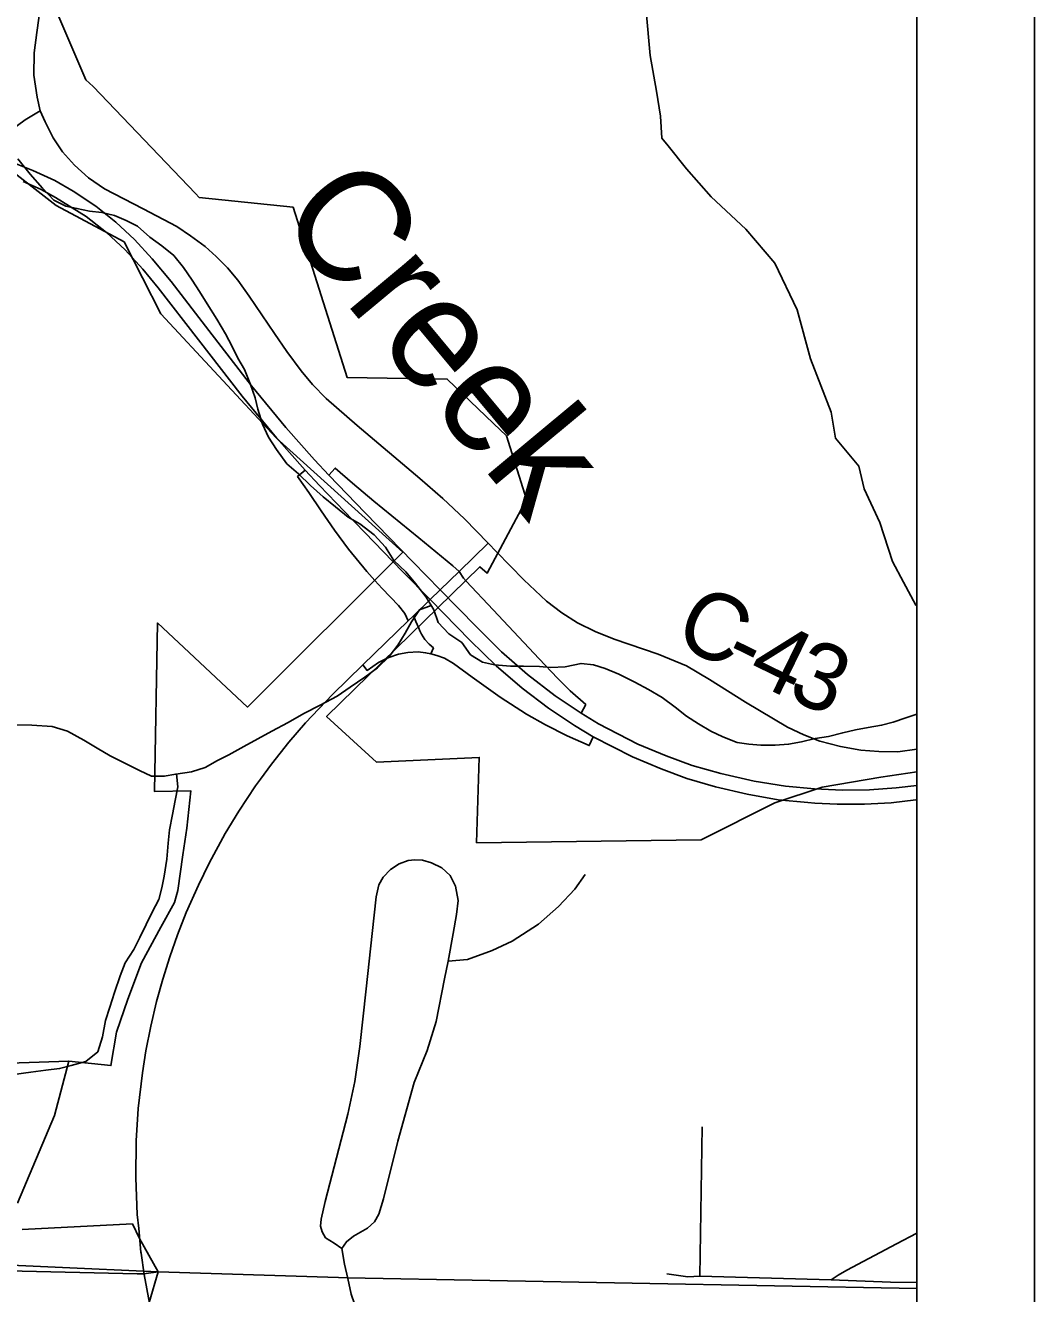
# Model space of a CAD drawing. Extents: x 0 to 34, y 0 to 22.
# Drawn here: x 8.143 to 9, y 15.691 to 16.768 of the extents above; entities that cross this region are included whole.
import ezdxf

# ---------------------------------------------------------------- set-up
doc = ezdxf.new("R2010")
doc.units = 0
for name, color, linetype in [('GM_X_City_Street', 7, 'Continuous'), ('GM_X_Corporation', 7, 'Continuous'), ('GM_X_County_Road', 7, 'Continuous'), ('GM_X_County_Road_Text', 7, 'Continuous'), ('GM_X_Interchange_Ramps', 7, 'Continuous'), ('GM_X_Minor_River', 7, 'Continuous'), ('GM_X_Minor_River_Text', 7, 'Continuous'), ('GM_X_Township_Road', 7, 'Continuous'), ('GM_X_US_Route', 7, 'Continuous'), ('SH_Data', 7, 'Continuous')]:
    doc.layers.add(name, color=color, linetype=linetype)

msp = doc.modelspace()

# ---------------------------------------------------------------- linework, layer by layer
at = {"layer": 'GM_X_City_Street'}
msp.add_line((8.7156, 15.7058), (8.7176, 15.8327), dxfattribs=at)
for points in [[(8.4116, 15.7295), (8.4052, 15.734), (8.3978, 15.7385), (8.3949, 15.7435), (8.3935, 15.7485), (8.394, 15.7542), (8.3975, 15.7693), (8.4166, 15.8435), (8.4228, 15.8711), (8.4269, 15.9008), (8.4323, 15.95), (8.4374, 15.997), (8.4408, 16.028), (8.443, 16.0382), (8.4468, 16.0448), (8.4531, 16.0513), (8.4603, 16.056), (8.4681, 16.059), (8.4737, 16.0596), (8.4801, 16.0593), (8.4879, 16.0569), (8.4967, 16.0527), (8.5037, 16.0461), (8.5083, 16.037), (8.5103, 16.025), (8.5091, 16.0131), (8.5063, 15.997), (8.5019, 15.9735)], [(8.4116, 15.7295), (8.4156, 15.7351), (8.4215, 15.74), (8.4334, 15.7467), (8.4393, 15.7521), (8.4431, 15.7586), (8.4471, 15.7716), (8.4592, 15.8206), (8.473, 15.8705), (8.4842, 15.8975), (8.4918, 15.9222), (8.4987, 15.9583), (8.5019, 15.9735), (8.5184, 15.9748), (8.5392, 15.9826), (8.5563, 15.9905), (8.5787, 16.0048), (8.5957, 16.0199), (8.6095, 16.0345), (8.6183, 16.0469)], [(8.8272, 15.7027), (8.8332, 15.7068), (8.8405, 15.7109), (8.8828, 15.7333), (8.9, 15.7424)], [(8.5748, 15.5168), (8.5674, 15.5329), (8.5596, 15.5459), (8.5504, 15.5583), (8.5375, 15.5703), (8.5256, 15.5803), (8.5129, 15.5913), (8.4865, 15.6143), (8.4598, 15.6377), (8.4342, 15.6605), (8.4251, 15.6741), (8.4195, 15.6907), (8.4166, 15.704), (8.4139, 15.716), (8.4116, 15.7295)], [(8.6876, 15.7079), (8.7056, 15.7053), (8.7156, 15.7058), (8.8272, 15.7027), (8.8777, 15.7009), (8.9, 15.7006)]]:
    msp.add_lwpolyline(points, dxfattribs=at)
at = {"layer": 'GM_X_Corporation'}
for points in [[(8.9, 14.1), (8.9, 16.1343), (8.8694, 16.1296), (8.8197, 16.1212), (8.7793, 16.1079), (8.7168, 16.0765), (8.5261, 16.074), (8.5283, 16.1464), (8.4411, 16.1423), (8.3987, 16.1812), (8.5289, 16.3083), (8.535, 16.3029), (8.5686, 16.3654), (8.5515, 16.4194), (8.5404, 16.43), (8.5011, 16.4677), (8.4163, 16.469), (8.3703, 16.6136), (8.2905, 16.622), (8.2873, 16.6254), (8.2004, 16.7162), (8.1943, 16.7219), (8.1619, 16.7973)], [(8.1333, 16.643), (8.1691, 16.615), (8.2267, 16.5842), (8.2579, 16.523), (8.3559, 16.4178), (8.4634, 16.3208), (8.3315, 16.1892), (8.2551, 16.2606), (8.2525, 16.1175), (8.2835, 16.118), (8.2799, 16.0863), (8.2766, 16.0638), (8.2725, 16.0333), (8.2695, 16.0233), (8.2578, 16.0023), (8.2416, 15.972), (8.2299, 15.9412), (8.2204, 15.9131), (8.2155, 15.8847), (8.1797, 15.8886), (8.1677, 15.8423), (8.1361, 15.768)], [(5.4664, 15.7674), (5.6014, 15.7658), (5.6068, 15.7657), (5.6123, 15.7657), (5.7944, 15.7634), (6.4702, 15.7474), (6.8105, 15.7443), (6.8653, 15.7428), (6.9267, 15.7411), (7.0294, 15.7382), (7.1916, 15.7337), (7.2174, 15.7331), (7.2238, 15.7321), (7.3532, 15.7283), (7.8346, 15.7173), (8.2379, 15.708), (8.2436, 15.7079), (8.2556, 15.7096), (8.4088, 15.7047), (8.4164, 15.7046), (8.9, 15.6953), (8.9, 16.3396)], [(7.9095, 15.8794), (8.1797, 15.8886), (8.1677, 15.8423), (8.1361, 15.768)], [(4.5503, 14.1), (8.9, 14.1), (8.9, 15.6953), (8.4164, 15.7046), (8.4088, 15.7047), (8.2556, 15.7096), (8.2436, 15.7079), (8.2379, 15.708), (7.8346, 15.7173), (7.3532, 15.7283), (7.2238, 15.7321), (7.2174, 15.7331), (7.1916, 15.7337), (7.0294, 15.7382), (6.9267, 15.7411), (6.8653, 15.7428), (6.8105, 15.7443), (6.4702, 15.7474), (5.7944, 15.7634), (5.6123, 15.7657), (5.6068, 15.7657), (5.6014, 15.7658), (5.4664, 15.7674)], [(8.1401, 15.7454), (8.2338, 15.7502), (8.2399, 15.7379), (8.2556, 15.7096), (8.2481, 15.6836)], [(8.0803, 15.7176), (8.2556, 15.7096), (8.2481, 15.6836)]]:
    msp.add_lwpolyline(points, dxfattribs=at)
at = {"layer": 'GM_X_County_Road'}
for p, q in [((8.5112, 16.3042), (8.536, 16.3283)), ((8.536, 16.3283), (8.5431, 16.3211)), ((8.241, 15.7263), (8.2391, 15.7464))]:
    msp.add_line(p, q, dxfattribs=at)
for points in [[(8.1571, 16.795), (8.1527, 16.7621), (8.1504, 16.7449), (8.1501, 16.7257), (8.1528, 16.7071), (8.1555, 16.6954)], [(8.1555, 16.6954), (8.1596, 16.6861), (8.1664, 16.6727), (8.1745, 16.6607), (8.1845, 16.6494), (8.1965, 16.6385), (8.21, 16.6294), (8.243, 16.6122), (8.2715, 16.5972), (8.2831, 16.5895), (8.2955, 16.5802), (8.305, 16.5719), (8.3144, 16.5621), (8.3232, 16.5516), (8.333, 16.5382), (8.3544, 16.5065), (8.3648, 16.4912), (8.3772, 16.4746), (8.3868, 16.4632), (8.3983, 16.4513), (8.4248, 16.4284), (8.4779, 16.3832), (8.4973, 16.3664), (8.5157, 16.3491), (8.536, 16.3283)], [(8.5431, 16.3211), (8.5663, 16.2972), (8.5854, 16.2792), (8.5986, 16.2692), (8.6118, 16.2607), (8.6267, 16.2533), (8.6428, 16.2468), (8.6802, 16.2342), (8.7043, 16.2241), (8.7238, 16.2127), (8.7545, 16.1933), (8.7902, 16.172), (8.804, 16.1656), (8.8176, 16.1603), (8.8352, 16.1556), (8.8524, 16.1526), (8.8677, 16.1515), (8.8839, 16.1513), (8.9, 16.1534)], [(8.3426, 16.1279), (8.352, 16.1408), (8.3666, 16.1593), (8.3809, 16.1758), (8.4038, 16.1999), (8.4296, 16.225), (8.468, 16.2624), (8.4725, 16.2667), (8.4866, 16.2805), (8.4952, 16.2887), (8.5112, 16.3042)], [(8.2391, 15.7464), (8.2379, 15.7584), (8.2366, 15.7895), (8.2369, 15.8208), (8.2387, 15.8482), (8.2423, 15.8786), (8.2452, 15.8973), (8.2493, 15.9182), (8.2543, 15.9391), (8.2595, 15.9581), (8.2657, 15.977), (8.2721, 15.9959), (8.2795, 16.0148), (8.2898, 16.038), (8.2989, 16.0566), (8.3125, 16.0817), (8.3241, 16.1007), (8.3384, 16.1222), (8.3426, 16.1279)], [(8.2497, 15.677), (8.2483, 15.683), (8.2437, 15.7073), (8.2411, 15.7253), (8.241, 15.7263)]]:
    msp.add_lwpolyline(points, dxfattribs=at)
at = {"layer": 'GM_X_Interchange_Ramps'}
for points in [[(8.3804, 16.3903), (8.3741, 16.3849), (8.3835, 16.3714), (8.394, 16.3557), (8.4054, 16.3394), (8.4174, 16.3234), (8.433, 16.3042), (8.4398, 16.2966)], [(8.5112, 16.3042), (8.506, 16.3091), (8.4771, 16.3328), (8.4389, 16.3641), (8.4208, 16.3792), (8.4061, 16.3921), (8.4006, 16.3861)], [(8.4398, 16.2966), (8.446, 16.2898), (8.4598, 16.2754), (8.4651, 16.2687), (8.468, 16.2624)], [(8.5172, 16.2962), (8.515, 16.2986), (8.5112, 16.3042)], [(8.6148, 16.184), (8.6188, 16.1913), (8.6055, 16.2029), (8.5947, 16.2137), (8.5791, 16.2301), (8.5402, 16.2717), (8.5172, 16.2962)], [(8.4725, 16.2667), (8.4745, 16.262), (8.4769, 16.2563)], [(8.4769, 16.2563), (8.4779, 16.254), (8.4793, 16.2512), (8.4822, 16.2467), (8.4858, 16.2427), (8.4894, 16.2394), (8.4873, 16.2344)], [(8.4496, 16.2303), (8.4515, 16.2312), (8.4598, 16.2341), (8.4677, 16.2356), (8.4765, 16.236), (8.4828, 16.2353), (8.4873, 16.2344), (8.4922, 16.233), (8.4988, 16.2306), (8.5066, 16.2263), (8.5223, 16.2147), (8.546, 16.1975), (8.5684, 16.1831), (8.5846, 16.174), (8.6031, 16.1647), (8.6217, 16.1565), (8.6251, 16.1639)], [(8.4296, 16.225), (8.4331, 16.2203), (8.4428, 16.227), (8.4496, 16.2303)]]:
    msp.add_lwpolyline(points, dxfattribs=at)
at = {"layer": 'GM_X_Minor_River'}
for points in [[(8.9, 16.2749), (8.8992, 16.2758), (8.8886, 16.2953), (8.8793, 16.3127), (8.8685, 16.3459), (8.8551, 16.3746), (8.8506, 16.3939), (8.8309, 16.4175), (8.8271, 16.4395), (8.8097, 16.4848), (8.7983, 16.5265), (8.7795, 16.5661), (8.7548, 16.5949), (8.7252, 16.6226), (8.7043, 16.6462), (8.6889, 16.6657), (8.6835, 16.6724), (8.6824, 16.691), (8.679, 16.7123), (8.6735, 16.7426), (8.6702, 16.7801)], [(8.9, 16.1833), (8.8907, 16.1801), (8.8798, 16.1763), (8.87, 16.1737), (8.8586, 16.1718), (8.848, 16.17), (8.8371, 16.1674), (8.825, 16.1643), (8.8137, 16.1625), (8.802, 16.1598), (8.791, 16.1576), (8.7797, 16.1568), (8.7675, 16.1568), (8.7572, 16.1577), (8.7473, 16.1592), (8.7353, 16.1638), (8.7249, 16.1688), (8.7145, 16.175), (8.7044, 16.1815), (8.6946, 16.1892), (8.6837, 16.1972), (8.6721, 16.2041), (8.6605, 16.2102), (8.647, 16.217), (8.6354, 16.2219), (8.6254, 16.225), (8.6148, 16.2262), (8.6012, 16.2235), (8.589, 16.2228), (8.5795, 16.2236), (8.5658, 16.2239), (8.5548, 16.224), (8.5414, 16.2251), (8.5311, 16.2274), (8.521, 16.2336), (8.5135, 16.244), (8.5026, 16.2513), (8.4935, 16.2609), (8.4898, 16.2718), (8.4833, 16.2826), (8.4742, 16.2941), (8.4659, 16.3041), (8.4558, 16.3137), (8.4486, 16.3249), (8.4391, 16.3356), (8.427, 16.3447), (8.417, 16.3505), (8.4064, 16.3593), (8.3959, 16.3677), (8.385, 16.3773), (8.3748, 16.3872), (8.365, 16.3957), (8.3562, 16.408), (8.3494, 16.4184), (8.3442, 16.4293), (8.3403, 16.4421), (8.3381, 16.4519), (8.334, 16.4632), (8.329, 16.4759), (8.3234, 16.4856), (8.3185, 16.4954), (8.3129, 16.5062), (8.3056, 16.5186), (8.2972, 16.5316), (8.2908, 16.542), (8.2844, 16.5517), (8.2773, 16.5625), (8.269, 16.5726), (8.2588, 16.581), (8.2487, 16.5883), (8.2381, 16.5975), (8.2285, 16.6025), (8.2185, 16.6067), (8.2077, 16.6091), (8.1974, 16.6103), (8.1867, 16.6126), (8.1772, 16.6146), (8.1671, 16.6196), (8.1573, 16.6299), (8.147, 16.6418), (8.1364, 16.6548)], [(8.4876, 16.2755), (8.4776, 16.2718), (8.4707, 16.2617), (8.4653, 16.252), (8.4592, 16.2419), (8.4519, 16.2322), (8.4419, 16.2224), (8.4311, 16.2145), (8.4188, 16.2061), (8.4077, 16.1985), (8.3931, 16.1909), (8.3793, 16.1836), (8.3662, 16.176), (8.3523, 16.1687), (8.3284, 16.1558), (8.3157, 16.1485), (8.306, 16.1437), (8.2955, 16.138), (8.2839, 16.1343), (8.2706, 16.1323), (8.2608, 16.1305), (8.2501, 16.1306), (8.2397, 16.1352), (8.2274, 16.1416), (8.215, 16.1477), (8.2038, 16.1542), (8.1925, 16.1611), (8.1786, 16.1686), (8.1656, 16.1728), (8.1484, 16.1738), (8.1309, 16.174)], [(8.2713, 16.1324), (8.2725, 16.1214), (8.2702, 16.1099), (8.2679, 16.098), (8.2653, 16.085), (8.2641, 16.0736), (8.263, 16.0599), (8.2608, 16.0457), (8.2588, 16.0358), (8.2561, 16.0258), (8.2507, 16.015), (8.2454, 16.0046), (8.24, 15.9934), (8.235, 15.9833), (8.2277, 15.9721), (8.2235, 15.9609), (8.2187, 15.9467), (8.2145, 15.9344), (8.211, 15.9229), (8.2084, 15.9091), (8.2043, 15.8965), (8.1943, 15.8882), (8.1818, 15.8847), (8.172, 15.8822), (8.1603, 15.8807), (8.1474, 15.8791), (8.133, 15.8772)]]:
    msp.add_lwpolyline(points, dxfattribs=at)
at = {"layer": 'GM_X_Township_Road'}
msp.add_lwpolyline([(8.1307, 16.6792), (8.1426, 16.6878), (8.1555, 16.6954)], dxfattribs=at)
at = {"layer": 'GM_X_US_Route'}
for points in [[(8.1279, 16.6534), (8.1493, 16.645), (8.1679, 16.6363), (8.1834, 16.6272), (8.2026, 16.6145), (8.2197, 16.6009), (8.2356, 16.5862), (8.2505, 16.5699), (8.2668, 16.5506), (8.2988, 16.5089), (8.335, 16.4619), (8.364, 16.4266), (8.3884, 16.3991), (8.4006, 16.3861), (8.4315, 16.3541), (8.4718, 16.3125), (8.4952, 16.2887), (8.5259, 16.2572), (8.5473, 16.2362), (8.5693, 16.2169), (8.5928, 16.1986), (8.6148, 16.184), (8.6296, 16.175), (8.6629, 16.1578), (8.6872, 16.1477), (8.7091, 16.1396), (8.7334, 16.1328), (8.7619, 16.1264), (8.7884, 16.1221), (8.813, 16.1197), (8.8368, 16.1187), (8.8598, 16.119), (8.8823, 16.1206), (8.9, 16.1227)], [(8.1411, 16.6356), (8.1563, 16.6288), (8.1686, 16.622), (8.1946, 16.6057), (8.2117, 16.5921), (8.2276, 16.5774), (8.2425, 16.5611), (8.2557, 16.5451), (8.2899, 16.5011), (8.327, 16.4531), (8.3561, 16.4178), (8.3804, 16.3903)], [(8.3804, 16.3903), (8.3926, 16.3773), (8.4209, 16.3479)], [(8.4209, 16.3479), (8.423, 16.3459), (8.4633, 16.3043), (8.4866, 16.2805), (8.5205, 16.2457), (8.5428, 16.2243), (8.5647, 16.2052), (8.5871, 16.1882), (8.6092, 16.1736), (8.6251, 16.1639), (8.6585, 16.1468), (8.6828, 16.1366), (8.7047, 16.1285), (8.7291, 16.1214), (8.756, 16.1151), (8.7823, 16.1105), (8.8074, 16.1081), (8.8134, 16.1077)], [(8.8134, 16.1077), (8.8322, 16.1067), (8.8556, 16.1068), (8.8783, 16.108), (8.899, 16.1103), (8.9, 16.1105)]]:
    msp.add_lwpolyline(points, dxfattribs=at)
at = {"layer": 'SH_Data'}
msp.add_line((9, 21), (9, 14), dxfattribs=at)
msp.add_lwpolyline([(2.1, 20.9), (8.9, 20.9), (8.9, 14.1), (2.1, 14.1)], close=True, dxfattribs=at)

# ---------------------------------------------------------------- texts
at = {"layer": 'GM_X_County_Road_Text'}
for s, rotation, p in [('C', 333.8324, (8.6915, 16.2446)), ('4', 333.9917, (8.754, 16.2139)), ('-', 333.8615, (8.7331, 16.2241)), ('3', 337.2119, (8.7884, 16.1972))]:
    msp.add_text(s, height=0.0568, rotation=rotation, dxfattribs=at).set_placement(p)
at = {"layer": 'GM_X_Minor_River_Text'}
msp.add_text('Creek', height=0.09471, rotation=309.7532, dxfattribs=at).set_placement((8.3547, 16.6044))

doc.saveas('drawing.dxf')
